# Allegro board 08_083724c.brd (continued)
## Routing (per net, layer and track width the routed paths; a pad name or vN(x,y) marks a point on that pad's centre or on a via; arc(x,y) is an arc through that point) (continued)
USB_PHY_DP: length 12.3
  TOP w0.133: v1(54.28,12.79) 54.53,12.54 54.53,11.39 54.41,11.27 P3.A6 54.49,10.44 54.49,9.85 54.53,9.8 54.53,9.8 P3.B6
  BOTTOM w0.133: U22.6 55.72,19.75 55.85,19.63 55.85,19.24 54.53,17.93 54.53,13.04 v1(54.28,12.79)
USB_PHY_ID: length 16.3
  TOP w0.14: v2(62.31,30.02) R39.2 62.31,32.19 S1.1A
  L3_SIG1 w0.114: v2(62.31,30.02) 61.23,28.94 61.23,21.45 v2(59.26,19.48)
  BOTTOM w0.14: U22.1 58.22,19.73 58.47,19.48 v2(59.26,19.48)
USB_PHY_REFCLK: length 4.1
  BOTTOM w0.14: R64.2 R217.2 61.43,20.55 60.32,21.65 U22.23
USB_PHY_RESET*: length 40.1
  TOP w0.14: v2(45.91,1.54) U4.5
  L3_SIG1 w0.114: v2(63.32,21.26) 60.73,18.67 48.03,18.67 46.43,17.07 46.43,2.06 v2(45.91,1.54)
  BOTTOM w0.14: v2(63.32,21.26) 62,21.26 61.43,21.83 R207.1 61.17,22.15 U22.22
USB_PHY_VBUS: length 4.9
  TOP w0.508: v2(60.01,19.42) 60.01,19.15 59.5,18.64 56.59,18.64
  BOTTOM w0.508: R218.1 v2(60.01,19.42)
USB_PHY_VBUS_EN: length 24.9
  TOP w0.14: v2(64.18,21.1) 63.26,22.02 R193.1
  L3_SIG1 w0.114: v2(50.5,16.31) 52.48,18.29 61.37,18.29 v2(64.18,21.1)
  BOTTOM w0.14: v2(50.5,16.31) 53.59,19.41 53.59,20.47 54.27,21.15 U22.7
USB_TYPEC: length 10.2
  TOP w0.305: P2.B4 70.06,9.32 P2.A9 70.06,11.49 ; P2.B9 67.56,9.32 P2.A4 67.56,11.41 67.13,11.84
  TOP w0.508: v2(70.68,13.59) C94.1 70.68,12.1 70.06,11.49 ; D1.1 v2(71.03,15.31) ; 67.13,11.84 D3.C v2(67.13,13.59)
  vias: v2(0.97,57.07) v2(0.97,56.31) v2(1.73,57.07) v2(1.73,56.31) v2(66.4,14.35) v2(66.4,13.59) v2(67.16,14.35)

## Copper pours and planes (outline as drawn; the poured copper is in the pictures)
1V8_LDO0 on TOP (solid shape): 8.71,31.04 6.17,31.04 6.05,31.17 6.05,32.18 6.3,32.44 8.71,32.44
1V8_LDO0 on BOTTOM (solid shape): 7.57,30.91 7.92,30.56 7.95,30.4 8.01,30.28 8.01,29.9 8.03,29.77 8.1,29.67 8.2,29.56 8.2,28.5 8.16,28.46 7.23,28.46 6.93,28.75 6.93,29.77 6.05,30.66 6.05,32.22 6.14,32.31 7.57,32.31
1V8_LDO2 on TOP (solid shape): 12.27,31.04 9.09,31.04 9.09,32.44 12.27,32.44
1V8_LDO2 on BOTTOM (solid shape): 10.62,32.22 10.62,31.55 11.2,30.96 11.2,28.93 11.21,28.85 11.23,28.78 11.23,28.63 10.99,28.63 10.99,29.62 10.94,29.62 10.94,29.63 10.41,30.15 10.17,30.15 9.98,30.15 9.09,31.04 9.09,32.31 10.53,32.31
1V8_LDO3 on TOP (solid shape): 15.82,32.18 15.82,31.29 15.57,31.04 12.65,31.04 12.65,32.44 15.57,32.44
1V8_LDO3 on BOTTOM (solid shape): 14.17,32.22 14.17,30.66 13.28,29.77 13.28,29.66 13.26,29.58 13.26,29.51 13.26,28.79 12.9,28.44 12.42,28.44 12.35,28.43 12.27,28.41 12.1,28.41 12.01,28.5 12.01,28.89 12.02,28.93 12.02,30.28 12.65,30.91 12.65,32.22 12.74,32.31 14.08,32.31
3V3 on TOP (solid shape): 11,23.29 11,20.75 9.22,20.75 9.22,23.29 9.47,23.55 10.74,23.55
3V3 on TOP (solid shape): 15.95,25.7 13.41,25.7 13.16,25.96 13.16,27.23 13.41,27.48 15.95,27.48
3V3 on BOTTOM (solid shape): 4.65,33.58 4.65,30.53 3.53,30.53 3.53,33.6 3.63,33.71 4.52,33.71
3V3 on BOTTOM (solid shape): 10.68,23.57 10.68,23.57 10.68,22.5 11.01,22.17 11.01,20.78 9.23,20.78 9.23,22.17 9.56,22.5 9.56,24.59 10.68,24.59
3V3 on BOTTOM (solid shape): 15.95,25.7 14.55,25.7 14.23,26.03 12.14,26.03 12.14,27.15 14.23,27.15 14.55,27.48 15.95,27.48
3V3 on BOTTOM (solid shape): 8.46,37.01 10.74,37.01 10.87,36.88 10.87,35.36 10.74,35.23 2.11,35.23 1.98,35.36 1.98,36.88 2.11,37.01 4.39,37.01 4.84,37.45 8.01,37.45
3V3 on BOTTOM: 56.59,20.62 57.35,20.62 57.35,14.91 57.61,14.66 58.75,14.66 58.88,14.53 58.88,13.89 58.75,13.77 56.72,13.77 56.59,13.89
3V3 on L6_PWR1: 52.2,15.98 58.52,15.98 58.78,15.72 58.78,14.2 58.37,13.79 53.31,13.79 48.41,8.89 42.06,8.89 38.81,5.64 38.81,4.5 38.3,3.99 21.54,3.99 19.25,6.27 17.35,6.27 16.97,6.65 16.97,8.18 17.09,8.31 25.22,8.31 27,6.53 35.38,6.53 35.76,6.15 36.65,6.15 37.8,7.29 37.8,8.56 36.65,9.7 36.65,10.21 38.28,11.84 48.06,11.84
3V3 on L10_SIG4: 4.78,47.29 2.43,44.95 2.43,6.97 3.57,5.83 17.16,5.83 17.67,6.34 17.67,9.83 16.08,11.42 16.08,32.5 10.93,37.64 10.93,45.52 9.16,47.29
DGND on L3_SIG1 (solid shape): 69.67,66.62 69.67,66.32 69.67,66.29 69.62,66.2 69.52,66.19 69.39,66.26 67.5,68.15 67.48,68.26 67.57,68.32 67.97,68.32
DGND on L3_SIG1 (solid shape): outline of 362 points within 29.83,64.65 35.97,67.38
DGND on L3_SIG1 (solid shape): outline of 406 points within 56.82,56.47 62.1,66.93
DGND on L10_SIG4 (solid shape): 29.49,61.65 29.58,61.59 29.56,61.48 27.41,59.32 27.3,59.3 27.23,59.39 27.11,59.64 26.85,59.74 26.78,59.73 26.71,59.72 26.62,59.73 26.58,59.81 26.58,60.14 28.09,61.65
DGND on L10_SIG4 (solid shape): 48.41,67.23 48.5,67.16 48.48,67.05 48.19,66.77 48.12,66.67 48.1,66.55 48.1,65.94 47.67,65.51 46.81,65.51 46.81,65.95 46.94,66.08 47,66.03 46.99,65.96 47.32,65.63 47.65,65.96 47.57,66.18 47.37,66.29 47.29,66.36 47.32,66.46 48.08,67.23
DGND on L10_SIG4 (solid shape): 47.65,62.2 47.72,62.14 47.86,61.97 48.07,61.91 48.27,61.96 48.41,62.1 48.48,62.15 48.57,62.12 51.87,58.82 51.87,58.09 51.81,57.99 51.7,58.02 50.88,58.83 50.88,59.39 50.86,59.48 50.81,59.57 49.21,61.17 49.12,61.23 49.02,61.25 48.21,61.25 47.49,61.97 47.46,62.06 47.5,62.13 47.53,62.15 47.56,62.18
DGND on L10_SIG4 (solid shape): outline of 430 points within 50.01,58.37 73.35,64.94
DGND on L10_SIG4 (solid shape): outline of 554 points within 56.44,64.87 67.66,66.87
DGND on TOP: 80.57,69.57 80.92,69.57 80.92,66.94 80.93,66.91 80.96,66.9 81.36,66.9 81.36,64.32 80.91,64.32 79.68,63.08 80.91,61.85 81.36,61.85 81.36,0.64 0.64,0.64 0.64,61.85 1.08,61.85 2.31,63.08 1.08,64.32 0.64,64.32 0.64,66.9 0.83,66.9 0.83,69.57 41.92,69.57 41.92,66.36 42.32,65.96 42.61,65.7 43,65.61 43.4,65.71 43.69,66 44.07,66.37 44.07,69.57 80.42,69.57 80.42,66.94 80.43,66.92 80.46,66.91 80.53,66.91 80.56,66.92 80.57,66.94 ; 6 cut-outs
DGND on TOP: 38.43,30.85 38.43,28.94 39,28.94 39,30.85
DGND on BOTTOM: 80.82,69.57 81.17,69.57 81.17,66.9 81.36,66.9 81.36,64.31 80.91,64.31 79.68,63.08 80.91,61.85 81.36,61.85 81.36,0.64 0.64,0.64 0.64,61.85 1.08,61.85 2.31,63.08 1.08,64.31 0.64,64.31 0.64,66.9 0.83,66.9 0.83,69.57 28.67,69.57 28.67,66.94 28.68,66.92 28.71,66.91 28.78,66.91 28.81,66.92 28.82,66.94 28.82,69.57 42.17,69.57 42.17,66.43 43,65.61 43.82,66.43 43.82,69.57 58.67,69.57 58.67,66.94 58.68,66.92 58.71,66.91 58.78,66.91 58.81,66.92 58.82,66.94 58.82,69.57 80.67,69.57 80.67,66.94 80.68,66.92 80.71,66.91 80.78,66.91 80.81,66.92 80.82,66.94 ; 64 cut-outs
DGND on L2_GND, L4_GND, L9_GND: 43.82,69.57 81.17,69.57 81.17,66.9 81.36,66.9 81.36,64.32 80.91,64.32 79.68,63.08 80.91,61.85 81.36,61.85 81.36,0.64 0.64,0.64 0.64,61.85 1.08,61.85 2.31,63.08 1.08,64.32 0.64,64.32 0.64,66.9 0.83,66.9 0.83,69.57 42.17,69.57 42.17,66.43 43,65.61 43.82,66.43 ; 2 cut-outs
DGND on L5_SIG2, L8_SIG3, L11_GND: 43.82,69.57 81.17,69.57 81.17,66.9 81.36,66.9 81.36,64.31 80.91,64.31 79.68,63.08 80.91,61.85 81.36,61.85 81.36,0.64 0.64,0.64 0.64,61.85 1.08,61.85 2.31,63.08 1.08,64.31 0.64,64.31 0.64,66.9 0.83,66.9 0.83,69.57 42.17,69.57 42.17,66.43 43,65.61 43.82,66.43
VDD_EXT on TOP (solid shape): 16.08,12.62 16.59,12.12 16.78,12.12 16.88,12.04 16.82,11.92 16.38,11.51 16.22,10.92 17.35,9.79 18.48,10.92 18.32,11.51 17.87,11.92 17.82,12.04 17.92,12.12 18.75,12.12 19.25,11.61 19.25,8.05 18.75,7.54 12.78,7.54 12.65,7.67 12.65,13.39 12.27,13.77 11.63,13.77 11.51,13.89 11.51,15.04 11.63,15.16 16.08,15.16
VDD_EXT on BOTTOM (solid shape): 64.72,51.36 64.47,51.1 63.96,51.1 63.7,51.36 63.7,53.77 63.96,54.03 64.72,54.03
VDD_EXT on BOTTOM (solid shape): outline of 83 points within 11.51,7.85 19.38,12.24
VDD_EXT on TOP: 55.29,62.74 55.29,61.35 48.97,61.35 48.97,62.74
VDD_EXT on TOP: 36.02,13.51 36.02,12.62 35.89,12.5 35.26,12.5 35.13,12.62 35.13,15.04 35.38,15.29 39.07,15.29 39.19,15.16 39.19,14.53 39.07,14.4 36.91,14.4
VDD_EXT on BOTTOM: 28.42,50.88 23.75,50.88 23.49,50.62 23.49,49.81 23.67,49.63 25.7,49.63 25.96,49.38 25.96,48.87 26.14,48.69 26.47,48.69 26.67,48.9 26.67,49.35 26.97,49.66 28.3,49.66 28.42,49.78
VDD_EXT on BOTTOM: 58.88,39.83 58.88,41.45 63.36,41.45 63.45,41.36 63.45,39.92 63.36,39.83
VDD_EXT on L6_PWR1: 43.82,69.57 81.17,69.57 81.17,66.9 81.36,66.9 81.36,64.31 80.91,64.31 79.68,63.08 80.91,61.85 81.36,61.85 81.36,0.64 0.64,0.64 0.64,61.85 1.08,61.85 2.31,63.08 1.08,64.31 0.64,64.31 0.64,66.9 0.83,66.9 0.83,69.57 42.17,69.57 42.17,66.43 43,65.61 43.82,66.43
VDD_INPUT on BOTTOM (solid shape): 3.25,43.48 3.25,42.95 3.86,42.34 5.19,42.34 5.28,42.25 5.28,41.83 3.82,41.83 3.57,41.58 2.11,41.58 1.98,41.71 1.98,43.48 2.11,43.61 3.12,43.61
VDD_INPUT on BOTTOM (solid shape): 6.81,56.27 5.89,56.27 5.54,55.91 5.54,53.62 5.5,53.51 5.49,53.4 5.5,53.29 5.53,53.19 5.54,53.18 5.54,53.14 5.92,52.76 8.46,52.76 8.84,53.14 8.84,53.2 8.87,53.3 8.88,53.4 8.87,53.49 8.84,53.59 8.84,55.91 8.48,56.27 7.57,56.27 7.57,56.67 9.62,56.67 10.11,56.18 10.11,55.04 11,54.15 11,51.7 10.91,51.61 3.47,51.61 3.38,51.7 3.38,54.15 4.27,55.04 4.27,56.18 4.76,56.67 6.81,56.67
VDD_INPUT on TOP: 5.28,52.82 10.05,52.82 10.24,52.63 10.24,50.98 8.39,49.14 8.39,43.99 8.9,43.48 11.63,43.48 11.89,43.23 11.89,41.71 11.63,41.45 8.97,41.45 7.7,42.72 5.16,42.72 3.89,41.45 2.11,41.45 1.98,41.58 1.98,43.61 2.11,43.74 4.14,43.74 4.46,44.06 4.46,51.99
VDD_INPUT on TOP: 55.07,21.77 53.16,21.77 52.15,20.75 50.88,20.75 50.88,22.66 50.62,22.91 48.84,22.91 48.72,23.04 48.72,24.18 48.84,24.31 52.53,24.31 52.65,24.18 52.65,22.78 53.16,22.28 55.07,22.28
VDD_INPUT on BOTTOM: 7.66,42.34 8.99,42.34 10.14,43.48 11.51,43.48 11.89,43.1 11.89,41.54 11.8,41.45 9.41,41.45 9.03,41.83 7.57,41.83 7.57,42.25
VDD_INPUT on L6_PWR1: 2.36,43.99 12.52,43.99 13.03,43.48 13.03,36.5 13.16,36.37 15.06,36.37 16.84,34.59 16.84,24.94 17.48,24.31 49.86,24.31 50.24,23.93 50.24,22.78 49.86,22.41 49.22,22.4 15.19,22.4 14.55,23.04 14.55,33.58 14.17,33.96 11.38,33.96 10.87,34.47 10.87,40.82 10.49,41.2 2.36,41.2 1.98,41.58 1.98,43.61
VDD_INT on TOP (solid shape): outline of 88 points within 20.27,22.78 26.62,32.18
VDD_INT on BOTTOM (solid shape): outline of 84 points within 22.94,24.94 29.03,32.18
VDD_INT on TOP: 25.79,59.61 25.79,57.52 27.44,57.52 27.44,59.61
VDD_INT on BOTTOM: 44.53,54.66 44.81,54.66 44.91,54.56 44.91,53.48 44.72,53.29 44.72,48.44 43.64,48.44 43.51,48.56 43.51,51.04 43.64,51.17 44.02,51.17 44.27,51.42 44.27,52.25 44.08,52.44 43.57,52.44 43.51,52.37 38.68,52.37 38.43,52.12 38.43,51.49 38.75,51.17 40.78,51.17 40.84,51.1 40.84,50.79 40.78,50.72 38.68,50.72 38.43,50.47 38.43,49.96 38.68,49.71 39.85,49.71 39.89,49.67 39.89,49.33 39.83,49.26 39.32,49.26 39.19,49.14 39.19,48.5 39.13,48.44 38.11,48.44 37.99,48.56 37.99,53.64 44.15,53.64 44.4,53.9 44.4,54.53
VDD_INT on BOTTOM: 41.16,49.58 41.16,49.14 40.97,48.95 40.46,48.95 40.4,48.88 40.4,48.55 40.49,48.46 41.57,48.46 41.67,48.56 41.67,49.58 41.61,49.64 41.22,49.64
VDD_INT on L7_PWR2: 55.58,62.03 55.58,48.56 59.96,44.18 59.96,33.2 63.83,29.32 63.83,24.69 47.83,8.69 21.79,8.69 20.14,7.04 6.68,7.04 4.01,9.7 4.01,27.1 5.92,29.01 11,29.01 12.14,30.15 12.14,48.06 26.81,62.73 26.81,67.3 27.57,68.06 38.75,68.06 39.45,67.36 39.45,63.87 40.19,63.13 45.95,63.13 46.36,62.73 54.88,62.73
VDD_LPDD4_IO on TOP (solid shape): 8.71,15.04 8.71,13.89 8.59,13.77 7.95,13.77 7.57,13.39 7.57,7.9 7.44,7.77 1.88,7.77 1.22,8.43 1.22,11.86 1.47,12.12 2.3,12.12 2.4,12.04 2.35,11.92 1.9,11.51 1.74,10.92 2.87,9.79 4,10.92 3.84,11.51 3.39,11.92 3.34,12.04 3.44,12.12 3.63,12.12 4.14,12.62 4.14,15.16 8.59,15.16
VDD_LPDD4_IO on BOTTOM (solid shape): outline of 83 points within 1.27,7.85 8.71,12.24
VDD_LPDD4_IO on TOP: 39.89,26.85 39.89,26.59 40.02,26.47 41.27,26.47 41.5,26.24 41.5,25.1 41.25,24.84 40.44,24.84 40.18,25.1 40.18,25.2 40.11,25.27 40.01,25.27 39.9,25.17 39.9,24 39.93,23.98 41.35,23.98 42.14,24.77 42.14,26.14 42.43,26.43 42.71,26.43 42.81,26.53 42.81,26.85 42.62,27.04 40.08,27.04
VDD_LPDD4_IO on TOP: 46.51,30.21 47,30.21 47.13,30.09 47.13,29.58 46.88,29.32 46.88,28.94 47.13,28.69 47.13,28.05 46.75,28.05 46.51,28.29
VDD_LPDD4_IO on TOP: 37.41,30.78 37.41,29.01 37.54,28.88 37.92,28.88 37.99,28.94 37.99,30.78 37.92,30.85 37.48,30.85
VDD_LPDD4_IO on TOP: 34.91,30.78 34.91,28.92 34.81,28.82 34.3,28.82 34.24,28.88 34.24,30.72 34.37,30.85 34.85,30.85
VDD_LPDD4_IO on TOP: 45.22,30.85 44.72,30.85 44.65,30.78 44.65,28.05 45.29,28.05 45.29,30.78
VDD_LPDD4_IO on BOTTOM: 37.86,47.17 37.86,46.27 38.07,46.05 39.03,46.05 39.64,46.66 42.37,46.66 42.9,46.13 44.63,46.13 44.72,46.22 44.72,47.17 44.65,47.23 37.92,47.23
VDD_LPDD4_IO on BOTTOM: 37.99,44.95 37.99,44.5 38.11,44.37 38.49,44.37 38.68,44.18 38.68,43.43 38.73,43.38 39.92,43.38 40.02,43.48 40.02,44.18 40.14,44.31 41.67,44.31 41.86,44.12 41.86,43.61 42.05,43.42 43.95,43.42 44.02,43.48 44.02,44.12 44.15,44.25 44.72,44.25 44.84,44.37 44.84,44.95
VDD_LPDD4_IO on L7_PWR2: 37.92,47.42 48.46,47.42 54.43,41.45 54.43,24.66 42.37,12.6 13.39,12.6 10.36,9.58 5.92,9.58 5.41,10.08 5.41,22.91 7.06,24.56 28.27,24.56 30.18,26.47 30.18,42.47 30.94,43.23 32.84,43.23 34.75,45.14 37.16,45.14 37.67,45.64 37.67,47.17
VDD_SOM on TOP: 1.24,69.44 5.74,69.44 5.74,64.74 5.56,64.57 1.4,64.57 1.24,64.72
VDD_SOM on BOTTOM: 1.02,69.44 5.51,69.44 5.51,64.66 5.42,64.57 1.17,64.57 1.02,64.72
VDD_SOM on L10_SIG4: 2.68,66.79 4.65,66.79 5.09,66.34 5.09,64.82 5.98,63.93 11.19,63.93 13.22,61.9 13.22,56.69 12.71,56.18 11.25,56.18 10.62,56.82 10.62,60.63 9.86,61.39 4.33,61.39 2.25,63.48 2.24,63.51 2.24,66.34
(no net) on TOP: 12.65,13.39 12.65,7.67 12.78,7.54 18.75,7.54 19.25,8.05 19.25,11.61 18.75,12.12 16.59,12.12 16.08,12.62 16.08,15.16 11.63,15.16 11.51,15.04 11.51,13.89 11.63,13.77 12.27,13.77
(no net) on TOP: 13.16,27.23 13.16,25.96 13.41,25.7 15.95,25.7 15.95,27.48 13.41,27.48
(no net) on TOP: 63.32,9.65 63.32,2.08 63.58,1.83 73.99,1.83 74.24,2.08 74.24,5.13 75.26,6.15 75.26,9.65
(no net) on TOP: 12.65,31.04 12.65,32.44 15.57,32.44 15.82,32.18 15.82,31.29 15.57,31.04
(no net) on TOP: 10.74,23.55 9.47,23.55 9.22,23.29 9.22,20.75 11,20.75 11,23.29
(no net) on TOP: 12.27,32.44 12.27,31.04 9.09,31.04 9.09,32.44
(no net) on TOP: 20.27,30.4 20.27,27.74 22.81,27.74 22.81,25.45 20.27,25.45 20.27,22.78 26.62,22.78 26.62,32.18 24.46,32.18 24.46,30.4
(no net) on TOP: 8.71,31.04 6.17,31.04 6.05,31.17 6.05,32.18 6.3,32.44 8.71,32.44
(no net) on TOP: 7.57,13.39 7.57,7.9 7.44,7.77 1.88,7.77 1.22,8.43 1.22,11.86 1.47,12.12 3.63,12.12 4.14,12.62 4.14,15.16 8.59,15.16 8.71,15.04 8.71,13.89 8.59,13.77 7.95,13.77
(no net) on TOP: 4.14,54.91 8.2,54.91 8.2,56.95 5.28,56.95 4.52,57.71 0.97,57.71 0.71,57.45 0.71,56.18 0.97,55.93 3.12,55.93
(no net) on TOP: 49.23,9.65 49.23,2.08 49.48,1.83 59.89,1.83 60.1,2.03 60.1,5.13 61.11,6.15 61.11,9.65
(no net) on BOTTOM: 11.25,30.91 11.25,28.63 10.94,28.63 10.94,29.63 10.41,30.15 9.98,30.15 9.09,31.04 9.09,32.31 10.53,32.31 10.62,32.22 10.62,31.55
(no net) on BOTTOM: 2.11,35.23 10.74,35.23 10.87,35.36 10.87,36.88 10.74,37.01 8.46,37.01 8.01,37.45 4.84,37.45 4.39,37.01 2.11,37.01 1.98,36.88 1.98,35.36
(no net) on BOTTOM: 19.38,9.12 19.38,12.24 11.51,12.24 11.51,7.85 18.11,7.85
(no net) on BOTTOM: 12.01,30.28 12.01,28.5 12.14,28.37 12.9,28.37 13.28,28.75 13.28,29.77 14.17,30.66 14.17,32.22 14.08,32.31 12.74,32.31 12.65,32.22 12.65,30.91
(no net) on BOTTOM: 1.27,17.25 1.27,12.62 8.71,12.62 8.71,18.08 8.59,18.21 2.24,18.21
(no net) on BOTTOM: 8.2,30.28 8.2,28.5 8.08,28.37 7.32,28.37 6.93,28.75 6.93,29.77 6.05,30.66 6.05,32.22 6.14,32.31 7.57,32.31 7.57,30.91
(no net) on BOTTOM: 3.47,51.61 10.91,51.61 11,51.7 11,54.15 10.11,55.04 10.11,56.18 9.62,56.67 7.57,56.67 7.57,56.27 8.48,56.27 8.84,55.91 8.84,53.14 8.46,52.76 5.92,52.76 5.54,53.14 5.54,55.91 5.89,56.27 6.81,56.27 6.81,56.67 4.76,56.67 4.27,56.18 4.27,55.04 3.38,54.15 3.38,51.7
(no net) on BOTTOM: 13.28,25.45 12.09,25.45 12.09,25.78 13.97,25.78 14.55,25.2 17.35,25.2 17.48,25.07 17.48,21.13 17.35,21.01 16.21,21.01 16.08,21.13 16.08,23.93 15.95,24.05 14.68,24.05
(no net) on BOTTOM: 19.38,16.81 19.38,12.62 11.51,12.62 11.51,18.08 11.63,18.21 17.98,18.21
(no net) on BOTTOM: 5.28,43.3 4.2,43.3 4.01,43.48 4.01,44.12 3.51,44.63 3.51,46.91 3.63,47.04 4.52,47.04 4.65,46.91 4.65,45.39 5.28,44.75 5.26,44.75 5.35,44.67 5.35,43.37
(no net) on BOTTOM: 22.94,24.94 28.91,24.94 29.03,25.07 29.03,32.05 28.91,32.18 22.94,32.18
(no net) on BOTTOM: 5.19,42.34 3.86,42.34 3.25,42.95 3.25,43.48 3.12,43.61 2.11,43.61 1.98,43.48 1.98,41.71 2.11,41.58 3.57,41.58 3.82,41.83 5.28,41.83 5.28,42.25
(no net) on BOTTOM: 64.72,54.03 64.72,51.36 64.47,51.1 63.96,51.1 63.7,51.36 63.7,53.77 63.96,54.03
(no net) on BOTTOM: 18.49,32.18 22.56,32.18 22.56,21.01 18.49,21.01 18.31,21.18 18.31,25.07 18.44,25.2 19.25,25.2 19.76,25.7 19.76,27.48 19.25,27.99 18.44,27.99 18.31,28.12 18.31,32
(no net) on BOTTOM: 11.25,23.42 11.25,24.61 10.92,24.61 10.92,22.73 11.51,22.15 11.51,19.35 11.63,19.23 15.57,19.23 15.7,19.35 15.7,20.5 15.57,20.62 12.78,20.62 12.65,20.75 12.65,22.02
(no net) on BOTTOM: 13.28,27.74 12.09,27.74 12.09,27.41 13.97,27.41 14.55,27.99 17.35,27.99 17.48,28.12 17.48,32.05 17.35,32.18 16.21,32.18 16.08,32.05 16.08,29.26 15.95,29.13 14.68,29.13
(no net) on BOTTOM: 4.52,33.71 3.63,33.71 3.53,33.6 3.53,30.53 4.65,30.53 4.65,33.58
(no net) on BOTTOM: 8.97,23.42 8.97,24.61 9.29,24.61 9.29,22.73 8.71,22.15 8.71,19.35 8.59,19.23 4.65,19.23 4.52,19.35 4.52,20.5 4.65,20.62 7.44,20.62 7.57,20.75 7.57,22.02
(no net) on BOTTOM: 1.27,8.69 1.27,12.24 8.71,12.24 8.71,7.85 2.11,7.85
(no net) on BOTTOM: 14.23,27.15 12.14,27.15 12.14,26.03 14.23,26.03 14.55,25.7 15.95,25.7 15.95,27.48 14.55,27.48
(no net) on BOTTOM: 10.68,22.5 10.68,24.59 9.56,24.59 9.56,22.5 9.23,22.17 9.23,20.78 11.01,20.78 11.01,22.17
(no net) on L3_SIG1: 43.82,69.57 81.17,69.57 81.17,66.9 81.36,66.9 81.36,64.31 80.91,64.31 79.68,63.08 80.91,61.85 81.36,61.85 81.36,0.64 0.64,0.64 0.64,61.85 1.08,61.85 2.31,63.08 1.08,64.31 0.64,64.31 0.64,66.9 0.83,66.9 0.83,69.57 42.17,69.57 42.17,66.43 43,65.61 43.82,66.43 ; 13 cut-outs
(no net) on L10_SIG4: 43.82,69.57 81.17,69.57 81.17,66.9 81.36,66.9 81.36,64.31 80.91,64.31 79.68,63.08 80.91,61.85 81.36,61.85 81.36,0.64 0.64,0.64 0.64,61.85 1.08,61.85 2.31,63.08 1.08,64.31 0.64,64.31 0.64,66.9 0.83,66.9 0.83,69.57 42.17,69.57 42.17,66.43 43,65.61 43.82,66.43
_N36 on BOTTOM: 58.37,39.83 58.37,41.45 52.63,41.45 52.34,41.16 52.34,40.37 52.88,39.83
_N299 on BOTTOM (solid shape): 8.71,18.08 8.71,12.62 4,12.62 4,14.29 3.91,14.5 3.7,14.59 2.04,14.59 1.83,14.5 1.74,14.29 1.74,12.62 1.27,12.62 1.27,17.25 2.24,18.21 8.59,18.21
_N307 on BOTTOM (solid shape): 17.48,32.05 17.48,28.12 17.35,27.99 14.55,27.99 13.97,27.41 12.09,27.41 12.09,27.65 12.27,27.65 12.35,27.63 12.42,27.62 13.07,27.62 13.23,27.66 13.36,27.74 13.95,28.34 14.01,28.41 14.05,28.5 14.05,28.51 14.68,29.13 15.95,29.13 16.08,29.26 16.08,32.05 16.21,32.18 17.35,32.18
_N331 on BOTTOM: 71.22,20.7 71.22,17.04 71.45,16.81 72.97,16.81 73.23,17.07 73.23,19.99 75.01,21.77 75.01,22.15 74.5,22.66 74.12,22.66 72.29,20.83 71.35,20.83
_N358 on BOTTOM (solid shape): 11.18,24.41 11.16,24.33 11.15,24.26 11.15,23.62 11.18,23.46 11.27,23.33 11.98,22.62 12.05,22.57 12.14,22.53 12.15,22.52 12.65,22.02 12.65,20.75 12.78,20.62 15.57,20.62 15.7,20.5 15.7,19.35 15.57,19.23 11.63,19.23 11.51,19.35 11.51,22.15 10.94,22.72 10.94,24.61 11.18,24.61
_N360 on BOTTOM (solid shape): 9.28,23.57 9.29,23.57 9.29,22.73 8.71,22.15 8.71,19.35 8.59,19.23 4.65,19.23 4.52,19.35 4.52,20.5 4.65,20.62 7.44,20.62 7.57,20.75 7.57,22.02 8.07,22.52 8.08,22.53 8.16,22.57 8.24,22.62 8.95,23.33 9.03,23.46 9.07,23.62 9.07,24.26 9.06,24.33 9.04,24.41 9.04,24.61 9.28,24.61
_N369 on TOP (solid shape): outline of 622 points within 63.32,1.83 75.26,9.65
_N376 on BOTTOM: 2.33,32.18 3.19,32.18 3.19,30.39 3.3,30.28 4.65,30.28 4.65,29.72 5.45,28.92 6.46,28.92 6.55,28.83 6.55,28.63 6.97,28.2 8.08,28.2 8.08,27.86 7.06,27.86 6.93,27.74 3.51,27.74 3.51,29.64 3.38,29.77 2.18,29.77 2.18,32.04
_N947 on BOTTOM (solid shape): 14.55,25.2 17.35,25.2 17.48,25.07 17.48,21.13 17.35,21.01 16.21,21.01 16.08,21.13 16.08,23.93 15.95,24.05 14.68,24.05 14.05,24.68 14.05,24.69 14.01,24.78 13.95,24.85 13.36,25.44 13.23,25.53 13.07,25.56 12.42,25.56 12.35,25.56 12.27,25.53 12.09,25.53 12.09,25.78 13.97,25.78
_N948 on BOTTOM (solid shape): 22.56,27.72 20.84,27.72 20.62,27.64 20.54,27.42 20.54,25.77 20.62,25.55 20.84,25.46 22.56,25.46 22.56,21.01 18.49,21.01 18.31,21.18 18.31,25.07 18.44,25.2 19.25,25.2 19.76,25.7 19.76,27.48 19.25,27.99 18.44,27.99 18.31,28.12 18.31,32 18.49,32.18 22.56,32.18
_N971 on BOTTOM: 6.12,42.12 6.73,42.12 6.73,41.76 6.6,41.63 6.6,40.64 8.14,39.1 8.14,38.47 8.01,38.34 4.84,38.34 4.71,38.47 4.71,39.1 6.25,40.64 6.25,41.63 6.12,41.76
_N973 on BOTTOM (solid shape): 4.65,46.91 4.65,45.39 5.27,44.77 5.26,44.75 5.32,44.7 5.32,43.81 5.33,43.76 5.35,43.7 5.35,43.37 5.28,43.3 4.2,43.3 4.01,43.48 4.01,44.12 3.51,44.63 3.51,46.91 3.63,47.04 4.52,47.04
_N1103 on BOTTOM (solid shape): 19.38,16.81 19.38,12.62 18.48,12.62 18.48,14.29 18.39,14.5 18.17,14.59 16.52,14.59 16.31,14.5 16.22,14.29 16.22,12.62 11.51,12.62 11.51,18.08 11.63,18.21 17.98,18.21
UART_3V3_IO on L5_SIG2: 77.74,34.34 67.26,34.34 67.07,34.15 67.07,32.05 71.32,27.8 71.32,21.2 70.37,20.24 70.37,19.35 73.16,16.56 80.21,16.56 80.4,16.75 80.4,18.15 80.09,18.47 80.09,31.99
UNNAMED_7_CAP_I120_N1 on TOP: 56.9,11.73 56.9,14.78 50.88,14.78 50.88,13.77 51.26,13.39 52.27,13.39 52.65,13 52.65,12.12 52.78,11.99 53.16,11.99 53.29,12.12 53.29,13 53.67,13.39 55.58,13.39 55.96,13 55.96,11.99 56.21,11.73
UNNAMED_7_CAP_I130_N1 on TOP (solid shape): outline of 622 points within 49.23,1.83 61.11,9.65
USB_PHY_VBUS on TOP: 50.88,15.29 56.9,15.29 56.9,19.81 56.34,20.37 56.34,23.42 56.08,23.67 53.16,23.67 53.16,22.91 53.29,22.78 55.45,22.78 55.58,22.66 55.58,21.39 55.45,21.26 53.29,21.26 52.4,20.37 50.88,20.37
USB_TYPEC on TOP (solid shape): 5.25,56.98 5.26,56.97 5.41,56.82 5.61,56.76 5.81,56.81 5.95,56.95 8.2,56.95 8.2,54.91 4.14,54.91 3.12,55.93 0.97,55.93 0.71,56.18 0.71,57.45 0.97,57.71 4.52,57.71
USB_TYPEC on BOTTOM (solid shape): 3,56.92 2.11,56.03 0.84,56.03 0.69,56.18 0.69,57.18 0.91,57.4 3,57.4
USB_TYPEC on BOTTOM: 72.97,13.39 71.83,13.39 71.32,12.88 71.32,12.12 71.2,11.99 70.56,11.99 70.43,12.12 70.43,12.88 69.98,13.34 66.29,13.34 66.14,13.49 66.14,15.19 66.5,15.54 72.85,15.54 73.1,15.29 73.1,13.51
USB_TYPEC on L7_PWR2: 43.82,69.57 81.17,69.57 81.17,66.9 81.36,66.9 81.36,64.31 80.91,64.31 79.68,63.08 80.91,61.85 81.36,61.85 81.36,0.64 0.64,0.64 0.64,61.85 1.08,61.85 2.31,63.08 1.08,64.31 0.64,64.31 0.64,66.9 0.83,66.9 0.83,69.57 42.17,69.57 42.17,66.43 43,65.61 43.82,66.43

Small or netless copper shapes (teardrops, artwork), in the pictures only: 1 on TOP, 3 on L10_SIG4

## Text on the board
User.Comments: 5.    SEE DETAIL B FOR Y1 AND Y2. | 7.    SMOOTHEN EDGES AND FREE FROM BURRS AFTER DEPANELIZATION PROCESS. | 4.    SEE DETAIL A FOR D3 AND D8. | 6.    SINGULATE BOARD AFTER ASSEMBLY PROCESS | DETAIL A | DETAIL B
Ref Des/Assembly Top: A | C
Ref Des/Silkscreen Top: EV-SC846-SOM | C | A | SD CARD | BMODE | USB2.0 | JTAG | UART
XSECTION_CHART: L1 | L2 | L3 | L4 | L5 | L6 | L7 | L8 | L9 | L10 | DESIGN CROSS SECTION CHART | ___________________________ | TOTAL THICKNESS 62 MIL | 1-10 | 1-2
PAGE_OUTLINE: FAB NOTES REVISION: 2ND NOVEMBER 2022 | 8.   IMPEDANCE REQUIREMENTS: IF NO STACKUP IS DEFINED, THE VENDOR IS ALLOWED TO ADJUST THE DIELECTRIC | 13.  PLATING SPECIFICATION: | 9.   FILLET OPTIONS TO ENHANCE RELIABILITY AT PAD JUNCTIONS WHERE SPACING PERMITS. | 10.  THIEVING: | 11.  LAYER TO LAYER REGISTRATION SHALL BE WITHIN 0.003 INCHES. | 12.  DRILL SIZES ARE FINISHED HOLE SIZES. ALL HOLES SHALL BE LOCATED WITHIN 0.005 INCHES DTP,UNLESS SPECIFIED. | 14.  SURFACE FINISH: | 15.  SOLDERMASK: | 1.   DIMENSIONS ARE IN INCHES (EXCEPT WHERE NOTED). | ALL DOCUMENTS & SPECIFICATIONS REFERRED TO BELOW SHOULD BE THE LATEST REVISIONS. | 2.  BOARD MATERIAL:(USE CHECKED ITEMS) | 3.   ALL LAMINATES & BONDING MATERIALS SHOULD BE SELECTED FROM IPC-4101 OR IPC-4103,(TG>170 DEGC TD>300 DEGC) | 4.   REFER TO IPC-6010 SERIES, CLASS 2 FOR FABRICATION. | 5.   REFER TO LAMINATION DIAGRAM FOR OVERALL BOARD THICKNESS, TOLERANCE APPLIES AFTER ALL LAMINATION AND PLATING | 6.   BOW & TWIST NOT TO EXCEED 0.0075 INCHES (0.75%) PER LINEAR INCH AND SHOULD BE MEASURED PER IPC-TM-650, METHOD 2.4.22. | 7.   ACCEPTABILITY PER ADI SPECIFICATION TST00115. | 16.  APPLY SILKSCREEN TO BOTH SIDES USING A NON-CONDUCTIVE, EPOXY BASED INK PER ARTWORK. | ( ) FILLETS ALLOWED | (X) FILLETS NOT ALLOWED | ( ) VENDOR MAY ADD THIEVING TO COMPENSATE FOR LOW COPPER DENSITY AREAS MAINTAINING A MINIMUM | (X) VENDOR MAY NOT ADD THIEVING TO COMPENSATE FOR LOW COPPER DENSITY AREAS. | (X) LPI | ( ) OTHER_________ | COLOR | ( ) GREEN | (X) OTHER: BLUE | (X) WHITE | ( ) OTHER | HINDER PROPER SOLDER WICKING. BARREL RELIEF ON SOLDERMASK ALLOWED IN UNFILLED VIA IN PAD HOLES. | (X) REFER TO LAMINATION DIAGRAM FOR FINISHED COPPER WEIGHT/THICKNESS REQUIRMENTS | (X) IMMERSION GOLD (ENIG) 1.58-3.94 MICRO INCHES OVER 118-236 MICRO INCHES MIN. OF ELECTROLESS NICKEL PER IPC-4552 | ( ) OSP (ORGANIC SOLDERABILITY PRESERVATIVE) | ( ) IMMERSION SILVER | ( ) SOFT WIRE BONDABLE GOLD 30-50 MICRO INCHES OF SOFT WIRE | (X) EDGE CONNECTOR FINGERS ARE TO BE PLATED WITH 100 MICRO-INCHES(.0001") OF LOW STRESS | THICKNESS & TRACE WIDTHS TO MEET THE IMPEDANCE REQUIREMENT. IF SPECIFIED, THE VENDOR MUST | TRACE WIDTH & SPACING THAT IMPACT THE REQUIREMENTS MUST HAVE WRITTEN APPROVAL FROM ADI. | MINIMUM BARREL PLATING OF 0.001 INCHES. PLATED HOLES SHALL NOT BE ROUGH OR IRREGULAR SO AS TO | SOLDERMASK OVER BARE COPPER OR BARE GOLD (BOTH SIDES) TO MEET IPC-SM-840. | IF PRESENT,DO NOT MODIFY SOLDERMASK DEFINED PADS (MASK OPENINGS LESS THAN COPPER PAD) WITHOUT APPROVAL. | MEET THE REQUIREMENTS LISTED IN THE IMPEDANCE TABLE. ANY ADJUSTMENT MADE TO THE DEFINED STACKUP, | PROCESSES. FINISHED THICKNESS MEASURED FROM TOP COPPER TO BOTTOM COPPER. | (X)  ISOLA 370HR OR S1000-2 OR IT180 OR EQUIVALENT | ( )  ISOLA-FR408HR OR EQUIVALENT | ( )  ISOLA IS410 | ( )  MEGTRON 6 | ( )  NELCO-4000-13 | ( )  ROGERS 4350B | ( )  ROGERS 3003 | ( )  ARLON 85N | ( )  EM370D | ( )  OTHER ________________________ | UL FLAMMABILITY RATING 94V-0. BOARD MATERIAL & CONSTRUCTION SHALL MEET THE REQUIREMENTS OF UL796/UL796F. | BONDABLE GOLD OVER 100-150 MICRO INCHES OF NICKEL | NICKEL UNDER 30 MICRO-INCHES (.0003') OF GOLD | 0.100 INCH CLEARANCE FROM ALL COPPER FEATURES, | THE STARTING COPPER WEIGHT/THICKNESS CAN VARY AS LONG AS THE FINISHED COPPER | WEIGHT/THICKNESS IS NOT LESS THAN THE SPECIFIED VALUE. | UNLESS OTHERWISE SPECIFIED | HOMOGENOUS MATERIALS IN THIS BOARD SHALL BE COMPLIANT WITH THE EU DIRECTIVE 2002/95/EC | WORKMANSHIP SHALL CONFORM TO IPC-A-600, CLASS 2. | 21.  INTENTIONAL SHORTS: | 17.  FINAL ELECTRICAL TEST TO BE PERFORMED USING PROVIDED IPC-D-356A NETLIST OR ODB++ FORMAT FILE. | 22.  PEMNUTS: | 23.  MANUFACTURER TO ETCH/STAMP WITH PERMANENT NON-CONDUCTIVE INK | ON SECONDARY SIDE UNLESS OTHERWISE SPECIFIED: | 18.  A TIME DOMAIN REFLECTOMETER REPORT (TDR) FOR EACH IMPEDANCE CONTROLLED LAYER & A CERTIFICATE | 19.  IF PRESENT, ALL BLIND/BURIED VIAS WITH AN ASPECT RATIO <1:1 TO BE PLATED SHUT WITH COPPER WHEN | 20.  FOR VIA FILL INFORMATION REFER TO DRILL CHART: | 24. PANELIZATION: | 25.  MINIMUM DESIGN LINE WIDTH IS .0042 INCHES. | 26.  MINIMUM DESIGN SPACING IS .004 INCHES. | IS ACCEPTABLE, ALL OTHER INSTANCES MUST BE REPORTED. | IF AN INTENTIONAL SHORT REPORT IS SUPPLIED AND DOES NOT MATCH THE FAB DATA THEN | THE PCB SHALL HAVE A VERIFICATION STAMP. | (X)  NON-CONDUCTIVE EPOXY FILL ALL 0.006 AND 0.010 INCHES DRILLED VIAS | ( )  COPPER FILL ALL 0.XXXX INCHES DRILLED VIAS | ( ) PEMNUTS TO BE INSTALLED BY FABRICATOR | ( ) PEMNUTS NOT TO BE INSTALLED BY FABRICATOR | (X) NOT APPLICABLE | USED AS VIA-IN-PAD OR AS A STACKED VIA. BLIND/BURIED VIAS WITH AN ASPECT RATIO >1:1 TO BE FILLED | A. UL CODE-FLAMMABILITY RATING FOR THOSE APPROVED MATERIALS(IF APPLICABLE) | B. DATE CODE | C. LOT NUMBER | D. MANUFACTURER LOGO | BOARDS TO BE SHIPPED IN ARRAY AND KEPT INTACT | PANEL TO BE SUBJECTED TO CUSTOMERS APPROVAL | PANEL SOLDER PASTE STENCIL GERBER TO BE PROVIDED TO ANALOG | CAN'T BE PERFORMED BECAUSE THE TRACE LENGTH IS TOO SHORT ON THE OUTER LAYERS AT THE PIN ESCAPES | ADI APPROVAL IS REQUIRED. | OF COMPLIANCE SHALL BE PROVIDED BY VENDOR AT TIME OF SHIPMENT. INSTANCES WHERE TDR TESTING | WITH NON-CONDUCTIVE EPOXY. | 12-LAYER STACKUP | TOOLING: | FINISH: | NOTES: | MATERIAL: | TESTING: | MISCELLANEOUS: | B | C | AS PER ECR-128314 | AS PER ECR-130698 | 07NOV25 | 27MAR26 | D. HARRINGTON | CUSTOMER EVALUATION Z
DIMENSION: DIA MAX/SEE NOTE 20 | BOARD THICKNESS AND CHAMFER | UNITS: INCH [MM] | EDGE FINGER DIMENSIONS | " " | POWER | JTAG | DSP | (REF) | QSPI | UART | FLASH
User.17: L2 GND | 08-      -07
User.18: L3 SIG | 08-      -08
User.19: L4 GND | 08-      -09
User.20: L5 SIG | 08-      -10
User.24: L6 PWR | 08-      -11
User.25: L7 PWR | 08-      -12
User.26: L8 SIG | 08-      -13
User.27: L9 GND | 08-      -14
User.28: L10 SIG | 08-      -15
User.29: L11 GND | 08-      -16
User.30: L8 SIG | 08-      -13
User.31: L9 GND | 08-      -14
User.32: DIA MAX/SEE NOTE 19 | 3 | 4 | BLIND VIAS L1-L3
User.36: DIA MAX/SEE NOTE 19 | 4 | BLIND VIAS L10-L12
User.45: FIGURE | SIZE | 8.0 | 6.0 | 10.0 | 12.0 | 16.0 | 29.0 | 45.0 | 126.0 | 48.0x24.0 | PLATED | NON-PLATED | FINISHED HOLES IN MILS | ALL UNITS ARE IN MILS | QTY | 30 | 905 | 826 | 3 | 28 | 20 | 12 | 2 | 8 | 1804 | TOLERANCE/NOTES | LPDDR4 | DSP | Decoupling | POWER | TOTAL HOLES: | eMMC | MicroSD | JTAG
